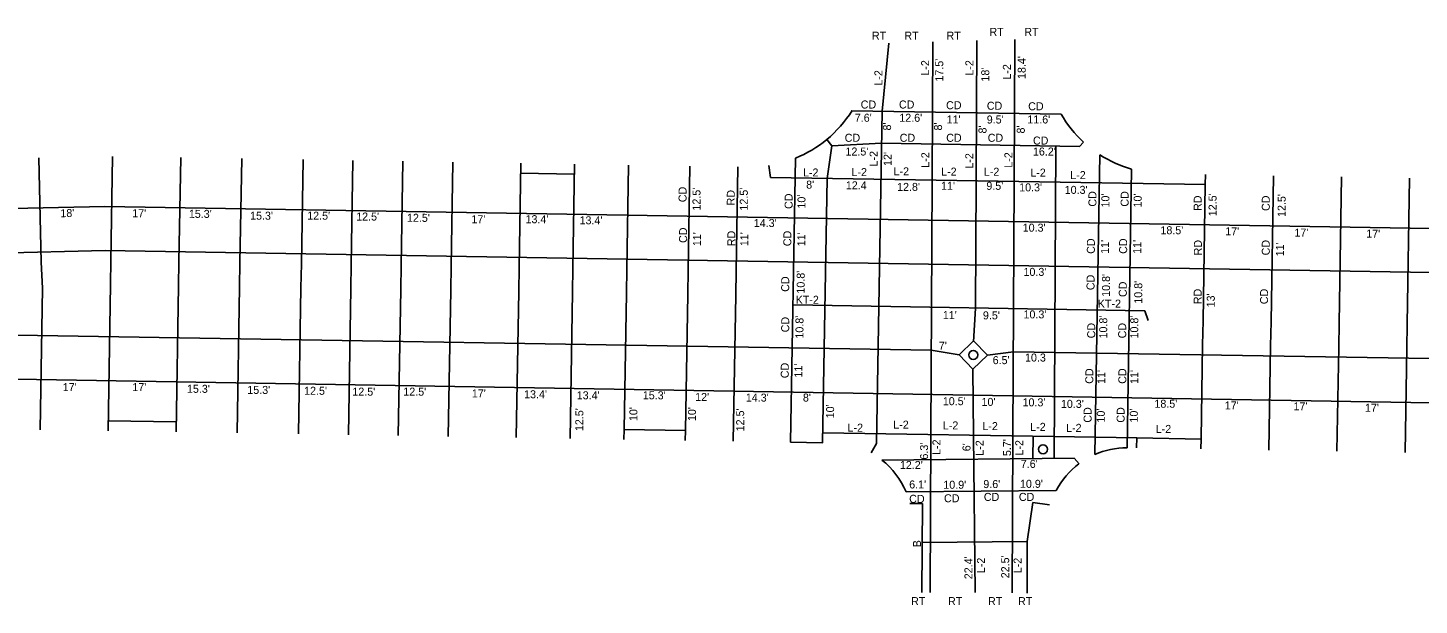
# Model space of a CAD drawing. Extents: x 4995357 to 4999033, y 3881202 to 3881750.
# Drawn here: x 4996781.3 to 4997128.9, y 3881593.7 to 3881737.8 of the extents above; entities that cross this region are included whole.
import ezdxf

# ---------------------------------------------------------------- set-up
doc = ezdxf.new("R2010")
doc.units = 0
for name, color, linetype in [('Draft_7', 7, 'Continuous'), ('dsn3DCenterLine', 7, 'Continuous'), ('dsn3DCurbFormgrade', 7, 'Continuous'), ('dsn3DCurbTop', 7, 'Continuous'), ('dsn3DDitchFront', 7, 'Continuous'), ('dsn3DDNC', 7, 'Continuous'), ('dsn3DExistingPvmtBtm', 7, 'Continuous'), ('dsn3DGroundLineIntercept', 7, 'Continuous'), ('dsn3DIntakeWell', 7, 'Continuous')]:
    doc.layers.add(name, color=color, linetype=linetype)

msp = doc.modelspace()

# ---------------------------------------------------------------- linework, layer by layer
at = {"layer": 'Draft_7'}
msp.add_line((4996976.96, 3881700.33), (4996976.96, 3881700.33), dxfattribs=at)
at = {"layer": 'dsn3DCurbFormgrade'}
for p, q in [((4996993.33, 3881634.04), (4996994.78, 3881717.04)), ((4996784.02, 3881705.38), (4996784.63, 3881679.38)), ((4996802.07, 3881679.73), (4996802.5, 3881705.73)), ((4996819.07, 3881679.45), (4996819.5, 3881705.45)), ((4996971.9, 3881634.41), (4996973.14, 3881705.31)), ((4996981.05, 3881700.26), (4996982.19, 3881708.41)), ((4997037.74, 3881630.34), (4997038.14, 3881708.32)), ((4996834.32, 3881679.2), (4996834.75, 3881705.19)), ((4996849.65, 3881678.94), (4996850.08, 3881704.94)), ((4996862.12, 3881678.74), (4996862.55, 3881704.73)), ((4996874.59, 3881678.53), (4996875.02, 3881704.52)), ((4996887.06, 3881678.32), (4996887.49, 3881704.32)), ((4996904.05, 3881678.04), (4996904.49, 3881704.04)), ((4996917.93, 3881703.81), (4996917.5, 3881677.82)), ((4996931.38, 3881703.59), (4996930.95, 3881677.59)), ((4996946.74, 3881703.33), (4996946.31, 3881677.34)), ((4996958.74, 3881703.13), (4996958.31, 3881677.14)), ((4996966.43, 3881703.45), (4996966.89, 3881700.5)), ((4996979.9, 3881634.27), (4996981.05, 3881700.26)), ((4997006.93, 3881636.32), (4997007.25, 3881699.83)), ((4997018.09, 3881667.89), (4997018.25, 3881699.64)), ((4997027.43, 3881635.98), (4997027.75, 3881699.49)), ((4997075.5, 3881698.69), (4997074.94, 3881664.7)), ((4997092.54, 3881700.91), (4997091.93, 3881664.42)), ((4997109.54, 3881700.63), (4997108.93, 3881664.13)), ((4997126.54, 3881700.35), (4997125.93, 3881663.85)), ((4996784.36, 3881637.52), (4996784.95, 3881672.88)), ((4996801.36, 3881637.24), (4996801.97, 3881673.73)), ((4996818.36, 3881636.96), (4996818.97, 3881673.45)), ((4996834.22, 3881673.2), (4996833.62, 3881636.7)), ((4996849.55, 3881672.94), (4996848.95, 3881636.45)), ((4996862.02, 3881672.74), (4996861.41, 3881636.24)), ((4996874.49, 3881672.53), (4996873.88, 3881636.03)), ((4996886.35, 3881635.83), (4996886.96, 3881672.32)), ((4996903.35, 3881635.54), (4996903.95, 3881672.04)), ((4996917.4, 3881671.82), (4996916.8, 3881635.32)), ((4996930.85, 3881671.59), (4996930.28, 3881637.6)), ((4996946.21, 3881671.34), (4996945.61, 3881637.34)), ((4996958.21, 3881671.13), (4996957.57, 3881634.64)), ((4997017.58, 3881659.49), (4997018.09, 3881667.89)), ((4997061.19, 3881664.77), (4997060.42, 3881667.19)), ((4997074.84, 3881658.7), (4997074.45, 3881635.2)), ((4997091.83, 3881658.42), (4997091.4, 3881632.42)), ((4997108.83, 3881658.13), (4997108.4, 3881632.14)), ((4997125.83, 3881657.85), (4997125.4, 3881631.86)), ((4997017.61, 3881636.15), (4997017.45, 3881652.62)), ((4996994.68, 3881629.94), (4997042.75, 3881630.39)), ((4997000.73, 3881621.99), (4997038.28, 3881622.35)), ((4997030.97, 3881609.62), (4997032.38, 3881619.35)), ((4997004.78, 3881609.37), (4997030.97, 3881609.62)), ((4997030.97, 3881609.62), (4997030.97, 3881596.7))]:
    msp.add_line(p, q, dxfattribs=at)
at = {"layer": 'dsn3DCurbTop'}
for p, q in [((4997045.05, 3881709.32), (4997044.04, 3881708.22)), ((4996784.95, 3881672.88), (4996784.63, 3881679.38)), ((4996801.97, 3881673.73), (4996802.07, 3881679.73)), ((4996818.97, 3881673.45), (4996819.07, 3881679.45)), ((4996834.32, 3881679.2), (4996834.22, 3881673.2)), ((4996849.65, 3881678.94), (4996849.55, 3881672.94)), ((4996862.12, 3881678.74), (4996862.02, 3881672.74)), ((4996874.59, 3881678.53), (4996874.49, 3881672.53)), ((4996887.06, 3881678.32), (4996886.96, 3881672.32)), ((4996904.05, 3881678.04), (4996903.95, 3881672.04)), ((4996917.5, 3881677.82), (4996917.4, 3881671.82)), ((4996930.95, 3881677.59), (4996930.85, 3881671.59)), ((4996946.21, 3881671.34), (4996946.31, 3881677.34)), ((4996958.21, 3881671.14), (4996958.31, 3881677.14)), ((4997074.84, 3881658.7), (4997074.94, 3881664.7)), ((4997091.83, 3881658.42), (4997091.93, 3881664.42)), ((4997108.83, 3881658.13), (4997108.93, 3881664.13)), ((4997125.93, 3881663.85), (4997125.83, 3881657.85)), ((4997043.95, 3881629), (4997042.75, 3881630.39))]:
    msp.add_line(p, q, dxfattribs=at)
at = {"layer": 'dsn3DDitchFront'}
msp.add_line((4996972.5, 3881668.65), (4997060.42, 3881667.19), dxfattribs=at)
at = {"layer": 'dsn3DDNC'}
for p, q in [((4996994.78, 3881717.04), (4996996.43, 3881734.05)), ((4997007.25, 3881699.83), (4997007.43, 3881734.36)), ((4997018.25, 3881699.64), (4997018.43, 3881734.67)), ((4997027.75, 3881699.49), (4997027.93, 3881734.93)), ((4996980.91, 3881709.96), (4996982.19, 3881708.41)), ((4996966.89, 3881700.5), (4997075.5, 3881698.69)), ((4997075.54, 3881701.19), (4997075.5, 3881698.69)), ((4996800.58, 3881693.26), (4996644.25, 3881689.61)), ((4996800.58, 3881693.26), (4997475, 3881682.06)), ((4996800.62, 3881682.26), (4996644.28, 3881678.6)), ((4996800.62, 3881682.26), (4997474.82, 3881671.06)), ((4996700.65, 3881662.42), (4997007.04, 3881657.33)), ((4997007.04, 3881657.33), (4997013.98, 3881656.23)), ((4997021.06, 3881656.11), (4997027.54, 3881656.98)), ((4997027.54, 3881656.98), (4997340.99, 3881651.78)), ((4996408.52, 3881656.27), (4997479.7, 3881638.47)), ((4996979.94, 3881636.77), (4997042.83, 3881635.73)), ((4997006.73, 3881596.88), (4997006.93, 3881636.32)), ((4997017.98, 3881596.83), (4997017.61, 3881636.15)), ((4997027.23, 3881596.78), (4997027.43, 3881635.98)), ((4996992.03, 3881631.71), (4996993.33, 3881634.04)), ((4997042.83, 3881635.73), (4997058.36, 3881635.47)), ((4997058.36, 3881635.47), (4997058.31, 3881632.97))]:
    msp.add_line(p, q, dxfattribs=at)
at = {"layer": 'dsn3DExistingPvmtBtm'}
for p, q in [((4996917.89, 3881701.31), (4996904.44, 3881701.54)), ((4996818.4, 3881639.46), (4996801.4, 3881639.74)), ((4997032.53, 3881635.9), (4997032.43, 3881630.29)), ((4997058.36, 3881635.47), (4997074.45, 3881635.19)), ((4997074.45, 3881635.19), (4997074.41, 3881632.7)), ((4997004.83, 3881619.09), (4997001.7, 3881619.09)), ((4997004.72, 3881596.89), (4997004.83, 3881619.09)), ((4997036.59, 3881618.74), (4997032.38, 3881619.35))]:
    msp.add_line(p, q, dxfattribs=at)
msp.add_lwpolyline([(4997021.06, 3881656.11), (4997017.46, 3881652.63), (4997013.98, 3881656.23), (4997017.58, 3881659.7)], close=True, dxfattribs=at)
msp.add_lwpolyline([(4996930.24, 3881635.1), (4996930.28, 3881637.6), (4996945.61, 3881637.34), (4996945.57, 3881634.84)], dxfattribs=at)
for centre in [(4997017.52, 3881656.17), (4997034.97, 3881632.63)]:
    msp.add_circle(centre, 1.12, dxfattribs=at)
at = {"layer": 'dsn3DGroundLineIntercept'}
for p, q in [((4996987.23, 3881717.16), (4997039.46, 3881716.3)), ((4996982.19, 3881708.41), (4996994.64, 3881709.04)), ((4996994.64, 3881709.04), (4997044.04, 3881708.22)), ((4997047.92, 3881631.32), (4997049.16, 3881706.14)), ((4997055.95, 3881633.01), (4997057.1, 3881702.54))]:
    msp.add_line(p, q, dxfattribs=at)
at = {"layer": 'dsn3DIntakeWell'}
for p, q in [((4996987.23, 3881717.16), (4997039.46, 3881716.3)), ((4997047.92, 3881631.32), (4997049.16, 3881706.14)), ((4997057.1, 3881702.54), (4997055.95, 3881633.01)), ((4997038.28, 3881622.35), (4997000.73, 3881621.99))]:
    msp.add_line(p, q, dxfattribs=at)
for points in [[(4996980.91, 3881709.96), (4996982.19, 3881708.41), (4996981.05, 3881700.26), (4996979.9, 3881634.27), (4996971.9, 3881634.41), (4996973.14, 3881705.31)], [(4997045.05, 3881709.32), (4997044.04, 3881708.22), (4996994.64, 3881709.04), (4996982.19, 3881708.41), (4996980.91, 3881709.96)], [(4996994.68, 3881629.94), (4997042.75, 3881630.39), (4997043.95, 3881629)]]:
    msp.add_lwpolyline(points, dxfattribs=at)
for centre, radius, start, end in [((4996961.81, 3881733.09), 30, 309.5528, 327.9393), ((4997065.4, 3881731.37), 30, 210.1572, 227.3028), ((4996961.81, 3881733.09), 30, 292.1917, 309.5528), ((4997065.4, 3881731.37), 30, 237.2311, 253.9459), ((4997055.96, 3881613.01), 20, 90.0536, 113.728), ((4996982.3, 3881614.23), 20, 22.8404, 51.7525), ((4997055.96, 3881613.01), 20, 126.9204, 152.153)]:
    msp.add_arc(centre, radius, start, end, dxfattribs=at)

# ---------------------------------------------------------------- texts
at = {"layer": 'dsn3DCenterLine'}
for s, p in [('RT', (4996992.21, 3881734.89)), ('RT', (4997000.31, 3881734.89)), ('RT', (4997010.84, 3881734.89)), ('RT', (4997021.57, 3881735.84)), ('RT', (4997030.28, 3881735.84)), ('CD', (4996989.41, 3881717.7)), ('CD', (4996998.96, 3881717.7)), ('CD', (4997010.74, 3881717.52)), ('CD', (4997020.92, 3881717.39)), ('CD', (4997031.25, 3881717.26)), ("7.6'", (4996987.93, 3881714.39)), ("12.6'", (4996999.05, 3881714.39)), ("11'", (4997010.87, 3881713.96)), ("9.5'", (4997020.9, 3881713.96)), ("11.6'", (4997031.04, 3881713.96)), ('CD', (4996985.41, 3881709.39)), ('CD', (4996999.15, 3881709.39)), ('CD', (4997010.77, 3881709.39)), ('CD', (4997021.14, 3881709.39)), ('CD', (4997032.44, 3881708.7)), ("12.5'", (4996985.6, 3881705.96)), ("16.2'", (4997032.44, 3881705.96)), ('L-2', (4996974.98, 3881700.73)), ('L-2', (4996987.1, 3881700.83)), ('L-2', (4996997.62, 3881701.01)), ('L-2', (4997009.5, 3881700.95)), ('L-2', (4997020.17, 3881700.92)), ('L-2', (4997031.78, 3881700.7)), ('L-2', (4997041.76, 3881700.08)), ("8'", (4996975.78, 3881697.7)), ('12.4', (4996985.69, 3881697.52)), ("12.8'", (4996998.5, 3881697.13)), ("11'", (4997009.48, 3881697.4)), ("9.5'", (4997020.8, 3881697.4)), ("10.3'", (4997029, 3881697.01)), ("10.3'", (4997040.37, 3881696.39)), ("10.3'", (4997029.88, 3881686.95)), ("18.5'", (4997064.29, 3881686.31)), ("17'", (4997080.48, 3881686.04)), ("17'", (4997097.77, 3881685.72)), ("17'", (4997115.72, 3881685.45)), ("10.3'", (4997030.08, 3881675.91)), ('KT-2', (4996973.15, 3881668.95)), ("11'", (4997009.92, 3881665.13)), ("9.5'", (4997019.94, 3881665.06)), ("10.3'", (4997030.08, 3881665.3)), ('KT-2', (4997048.64, 3881667.98)), ("7'", (4997008.92, 3881657.48)), ("6.5'", (4997022.38, 3881653.88)), ('10.3', (4997030.46, 3881654.53)), ("10.5'", (4997009.92, 3881643.63)), ("10'", (4997019.59, 3881643.45)), ("10.3'", (4997029.84, 3881643.35)), ("10.3'", (4997039.43, 3881642.96)), ("18.5'", (4997062.79, 3881643)), ("17'", (4997080.36, 3881642.57)), ("17'", (4997097.54, 3881642.35)), ("17'", (4997115.4, 3881641.98)), ('L-2', (4996997.54, 3881637.78)), ('L-2', (4997009.92, 3881637.58)), ('L-2', (4997019.81, 3881637.41)), ('L-2', (4997031.76, 3881637.22)), ('L-2', (4996986.12, 3881637.01)), ('L-2', (4997040.72, 3881636.97)), ('L-2', (4997063.11, 3881636.7)), ("12.2'", (4996999.2, 3881627.7)), ("7.6'", (4997029.4, 3881627.98)), ("6.1'", (4997001.52, 3881622.84)), ("10.9'", (4997010.05, 3881622.77)), ("9.6'", (4997020.04, 3881622.94)), ("10.9'", (4997029.2, 3881623)), ('CD', (4997001.52, 3881619.25)), ('CD', (4997010.22, 3881619.39)), ('CD', (4997020.17, 3881619.73)), ('CD', (4997028.92, 3881619.73)), ('RT', (4997002, 3881593.71)), ('RT', (4997011.23, 3881593.71)), ('RT', (4997021.22, 3881593.71)), ('RT', (4997028.72, 3881593.71))]:
    msp.add_text(s, height=2, dxfattribs=at).set_placement(p)
for s, rotation, p in [('L-2', 90, (4997006.51, 3881725.91)), ("17.5'", 90, (4997010.03, 3881724.42)), ('L-2', 90, (4997017.56, 3881725.91)), ("18.4'", 90, (4997030.63, 3881725.07)), ('L-2', 90, (4996994.83, 3881723.41)), ("18'", 90, (4997021.52, 3881724.42)), ('L-2', 90, (4997026.93, 3881724.91)), ("8'", 90, (4996996.99, 3881712.21)), ("8'", 90, (4997009.74, 3881712.21)), ("8'", 90, (4997020.84, 3881711.46)), ("8'", 90, (4997030.4, 3881711.46)), ('L-2', 90, (4996993.64, 3881703.22)), ("12'", 90, (4996997.14, 3881703.36)), ('L-2', 90, (4997006.55, 3881702.91)), ('L-2', 90, (4997017.54, 3881702.69)), ('L-2', 90, (4997027.31, 3881702.92)), ('CD', 90, (4996945.9, 3881694.31)), ("12.5'", 90, (4996949.38, 3881692.22)), ('RD', 90, (4996957.95, 3881693.51)), ("12.5'", 90, (4996961.2, 3881692.22)), ('CD', 90, (4996972.4, 3881692.62)), ("10'", 90, (4996975.61, 3881692.72)), ('CD', 90, (4997048.3, 3881693.2)), ("10'", 90, (4997051.54, 3881692.98)), ('CD', 90, (4997056.35, 3881693.2)), ("10'", 90, (4997059.6, 3881692.98)), ('RD', 90, (4997074.59, 3881692.12)), ("12.5'", 90, (4997078.32, 3881690.81)), ('CD', 90, (4997091.61, 3881692.12)), ("12.5'", 90, (4997095.58, 3881690.62)), ("18'", 1.2562, (4996789.46, 3881690.55)), ("17'", 359.8137, (4996807.4, 3881690.57)), ("15.3'", 359.8137, (4996821.54, 3881690.41)), ("15.3'", 359.8137, (4996836.84, 3881689.95)), ("12.5'", 359.8137, (4996851.11, 3881689.95)), ("12.5'", 359.8137, (4996863.35, 3881689.74)), ("12.5'", 359.8137, (4996876.04, 3881689.42)), ("17'", 359.8137, (4996892.14, 3881689.07)), ("13.4'", 359.8137, (4996905.66, 3881689.07)), ("13.4'", 359.8137, (4996919.16, 3881688.8)), ("14.3'", 359.8137, (4996962.69, 3881688.12)), ('CD', 90, (4996946.02, 3881684.13)), ("11'", 90, (4996949.51, 3881683.33)), ('RD', 90, (4996958.08, 3881683.33)), ("11'", 90, (4996961.32, 3881683.33)), ('CD', 90, (4996972.07, 3881683.33)), ("11'", 90, (4996975.57, 3881683.31)), ('CD', 90, (4997047.91, 3881681.42)), ("11'", 90, (4997051.43, 3881681.42)), ('CD', 90, (4997055.97, 3881681.42)), ("11'", 90, (4997059.48, 3881681.42)), ('RD', 90, (4997074.66, 3881681.03)), ('CD', 90, (4997091.61, 3881681.03)), ("11'", 90, (4997095.15, 3881680.8)), ('CD', 90, (4996971.54, 3881671.94)), ("10.8'", 90, (4996975.41, 3881671.49)), ('CD', 90, (4997047.83, 3881672.35)), ("10.8'", 90, (4997051.69, 3881670.68)), ('CD', 90, (4997055.89, 3881670.63)), ("10.8'", 90, (4997059.75, 3881668.97)), ('RD', 90, (4997074.59, 3881668.85)), ("13'", 90, (4997077.87, 3881668.05)), ('CD', 90, (4997091.18, 3881668.85)), ('CD', 90, (4996971.54, 3881661.82)), ("10.8'", 90, (4996975.11, 3881660.26)), ('CD', 90, (4997048, 3881660.31)), ("10.8'", 90, (4997051, 3881660.28)), ('CD', 90, (4997055.74, 3881660.31)), ("10.8'", 90, (4997058.75, 3881660.28)), ('CD', 90, (4996971.43, 3881650.37)), ("11'", 90, (4996974.83, 3881650.53)), ('CD', 90, (4997047.52, 3881648.97)), ("11'", 90, (4997050.53, 3881648.94)), ('CD', 90, (4997055.77, 3881648.97)), ("11'", 90, (4997058.77, 3881648.94)), ("17'", 359.8137, (4996790.03, 3881647.15)), ("17'", 359.8137, (4996807.42, 3881647.15)), ("15.3'", 359.8137, (4996821.07, 3881646.73)), ("15.3'", 359.8137, (4996836.15, 3881646.46)), ("12.5'", 359.8137, (4996850.34, 3881646.24)), ("12.5'", 359.8137, (4996862.39, 3881646.02)), ("12.5'", 359.8137, (4996875.12, 3881646.02)), ("17'", 359.8137, (4996892.24, 3881645.57)), ("13.4'", 359.8137, (4996905.3, 3881645.37)), ("13.4'", 359.8137, (4996918.45, 3881645.11)), ("15.3'", 359.8137, (4996934.96, 3881645.11)), ("12'", 359.8137, (4996948.04, 3881644.68)), ("14.3'", 359.8137, (4996960.7, 3881644.54)), ("8'", 359.8137, (4996974.96, 3881644.54)), ("12.5'", 90, (4996920.11, 3881637.16)), ("10'", 90, (4996933.61, 3881639.67)), ("10'", 90, (4996948.24, 3881639.67)), ("10'", 90, (4996982.76, 3881640.35)), ('CD', 90, (4997047.1, 3881639.26)), ('CD', 90, (4997055.35, 3881639.26)), ("12.5'", 90, (4996960.29, 3881637.1)), ("10'", 90, (4997050.39, 3881639.3)), ("10'", 90, (4997058.63, 3881639.3)), ("6.3'", 90, (4997006.23, 3881630.05)), ('L-2', 90, (4997009.34, 3881631.21)), ("6'", 90, (4997016.84, 3881632.13)), ('L-2', 90, (4997020.13, 3881631.01)), ("5.7'", 90, (4997026.96, 3881630.92)), ('L-2', 90, (4997030.02, 3881631.06)), ('B', 90, (4997004.47, 3881608.16)), ("22.4'", 90, (4997017.33, 3881600.17)), ('L-2', 90, (4997020.45, 3881601.69)), ("22.5'", 90, (4997026.51, 3881600.42)), ('L-2', 90, (4997029.6, 3881601.67))]:
    msp.add_text(s, height=2, rotation=rotation, dxfattribs=at).set_placement(p)

doc.saveas('drawing.dxf')
